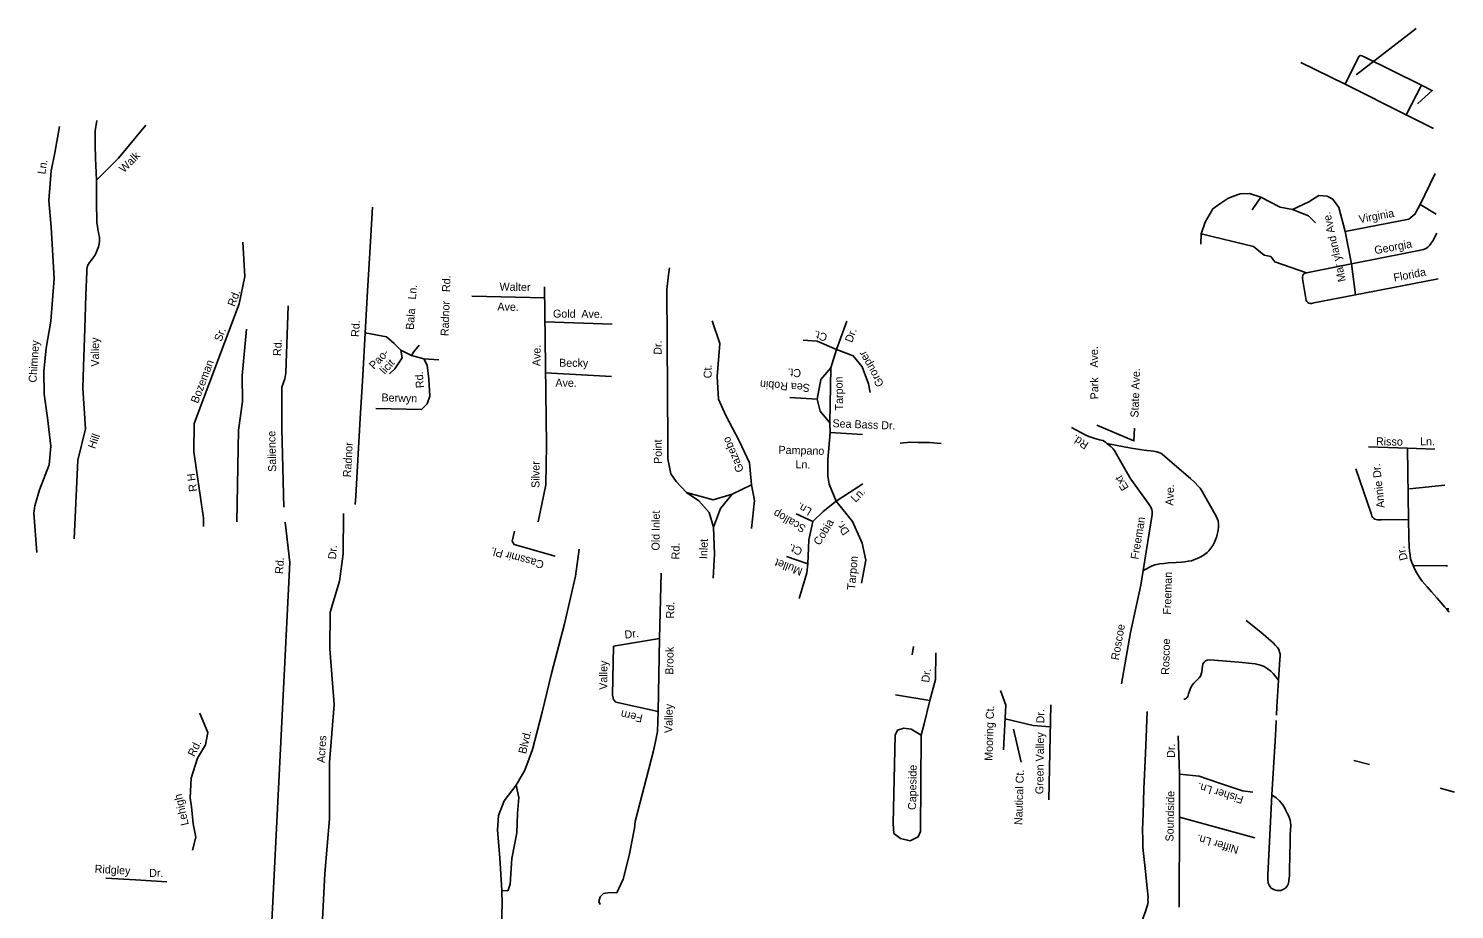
# Model space of a CAD drawing. Extents: x 2308163 to 2335412, y -96774 to 127732.
# Drawn here: x 2321991 to 2327836, y -48182 to -44573 of the extents above; entities that cross this region are included whole.
import ezdxf

# ---------------------------------------------------------------- set-up
doc = ezdxf.new("R2010")
doc.units = 0
doc.layers.add('Old_Level_10', color=7, linetype='Continuous')
doc.layers.add('Old_Level_35', color=7, linetype='Continuous')

msp = doc.modelspace()

# ---------------------------------------------------------------- linework, layer by layer
at = {"layer": 'Old_Level_10'}
for points in [[(2327678.5, -44572.8), (2327432.6, -44762.1)], [(2327745.2, -44824.8), (2327684.3, -44880.7)], [(2326523.7, -46210.6), (2326521.9, -46262.1), (2326369.2, -46197.5)], [(2326059.4, -47578.2), (2326027.9, -47443)]]:
    msp.add_lwpolyline(points, dxfattribs=at)
at = {"layer": 'Old_Level_35'}
for p, q in [((2327206.1, -44711.3), (2327387.1, -44800.8)), ((2327387.1, -44800.8), (2327638.1, -44926.8)), ((2327638.1, -44926.8), (2327701, -44805.4)), ((2327745.3, -44827.5), (2327701, -44805.4)), ((2327750.2, -44983), (2327638.1, -44926.8)), ((2327430.2, -45663.3), (2327413.2, -45536.7)), ((2322707.9, -46578.8), (2322669.1, -46307.3)), ((2327647.2, -46583.9), (2327642.9, -46292.4)), ((2323330.3, -46523), (2323332.3, -46488.5)), ((2322708, -46612.9), (2322707.9, -46578.8)), ((2325613.1, -47138.2), (2325617.8, -47104.3)), ((2327107.8, -47352.1), (2327113.9, -47242.5)), ((2326574.6, -47404.8), (2326575.9, -47370.7)), ((2327105.9, -47385.9), (2327107.8, -47352.1)), ((2326573.2, -47441.5), (2326574.6, -47404.8)), ((2327102.9, -47442.2), (2327100.9, -47491.3)), ((2327104.3, -47408.3), (2327102.9, -47442.2)), ((2327100.9, -47491.3), (2327087.7, -47712.1)), ((2327487.8, -47587.6), (2327423.2, -47571.1)), ((2327835.8, -47700.9), (2327777.6, -47684.6))]:
    msp.add_line(p, q, dxfattribs=at)
for points in [[(2327701, -44805.4), (2327462.8, -44687.6), (2327455.7, -44684), (2327449.8, -44683), (2327444.9, -44686), (2327442.8, -44690.1), (2327387.1, -44800.8)], [(2322099.2, -45082.6), (2322118.2, -44974.2)], [(2322269.8, -45194.2), (2322266.1, -45104.1), (2322264.4, -45051.1), (2322263.8, -45029.2), (2322264.7, -44992.1), (2322270.8, -44950.2)], [(2322472.4, -44968.1), (2322360.1, -45104.4), (2322269.8, -45194.2)], [(2322024.6, -46719.4), (2322012.8, -46558.4), (2322016.4, -46528.1), (2322036.4, -46462.8), (2322075.5, -46360.2), (2322083.1, -46284.4), (2322069.4, -46167.2), (2322055, -46070.3), (2322053.2, -45976.4), (2322064, -45882.9), (2322083.1, -45772), (2322096.7, -45597.4), (2322083.7, -45386.5), (2322074.7, -45277.1), (2322084, -45155.7), (2322099.2, -45082.6)], [(2327693.8, -45296.5), (2327756, -45166.6)], [(2322214.3, -46046.6), (2322216.4, -45957.4), (2322221.2, -45801.4), (2322225.5, -45664.6), (2322229.9, -45569.6), (2322230, -45558.5), (2322230.8, -45551.8), (2322232.4, -45544.5), (2322236.6, -45537.8), (2322241, -45531.9), (2322247.9, -45523), (2322255.2, -45513.1), (2322262.2, -45502.6), (2322267.9, -45491.7), (2322274, -45476.6), (2322277.3, -45466.6), (2322280, -45455.1), (2322281.4, -45444.6), (2322281.4, -45436.2), (2322281.3, -45427.7), (2322279.8, -45417.2), (2322278.3, -45408.7), (2322275.1, -45395.3), (2322273.2, -45383.1), (2322271.7, -45369.4), (2322269.8, -45280.3), (2322269.8, -45194.2)], [(2327413.2, -45536.7), (2327387.7, -45404.7), (2327361.4, -45306.2), (2327337.1, -45271.4), (2327314.2, -45260), (2327280.3, -45256.7), (2327239, -45282.9), (2327172.1, -45314.5), (2327121.5, -45304.3), (2327075.6, -45281.5), (2327042.3, -45263.4), (2326996, -45249.1), (2326957.8, -45249.9), (2326929.9, -45259.5), (2326906.2, -45269.3), (2326873.5, -45291.5), (2326845.2, -45311.8), (2326813.7, -45365.8), (2326797.1, -45414.1), (2326795.7, -45456.4)], [(2327042.3, -45263.4), (2327006.5, -45315.2)], [(2327387.7, -45404.7), (2327649.3, -45354.3), (2327673.4, -45334), (2327693.8, -45296.5)], [(2327761.2, -45333.6), (2327695, -45293.9)], [(2323332.3, -46488.5), (2323340.8, -46339.9), (2323350.8, -46170), (2323361.2, -45994.1), (2323371.3, -45819.4), (2323380.5, -45648.5), (2323390.3, -45491.7), (2323400.7, -45304.5)], [(2327172.1, -45314.5), (2327237.1, -45340.1), (2327265.8, -45368.7)], [(2327413.2, -45536.7), (2327641.4, -45491.2), (2327689.7, -45482.4), (2327702.8, -45479.7), (2327708.9, -45477.9), (2327715.9, -45474.9), (2327720.5, -45472.2), (2327726.1, -45468.3), (2327732.8, -45462), (2327740.4, -45452.6), (2327746.6, -45442.8), (2327763.7, -45411.3)], [(2322669.1, -46307.3), (2322670.1, -46191.4), (2322854.9, -45700.5), (2322877.1, -45588.4), (2322869.7, -45447.8)], [(2326797.1, -45414.1), (2327011.9, -45466), (2327055.3, -45501.5), (2327082.7, -45506.7), (2327098.9, -45528.4), (2327228.6, -45574.1)], [(2324797.1, -46824.3), (2324803.4, -46726.3), (2324798.5, -46616.4), (2324780.4, -46555.1), (2324738.7, -46507.4), (2324687.8, -46473.9), (2324646, -46429.1), (2324624, -46396.6), (2324611.6, -46335.5), (2324611, -46269.1), (2324606.7, -45642.1), (2324614.5, -45581.7), (2324618.4, -45553)], [(2327430.2, -45663.3), (2327259.4, -45697.1), (2327249.2, -45698.9), (2327244.8, -45698.9), (2327239.4, -45697.7), (2327235.3, -45695.5), (2327230.5, -45691.5), (2327227.3, -45686.4), (2327212.8, -45596.9), (2327212.9, -45590), (2327214, -45585), (2327216.1, -45580), (2327218.1, -45577.7), (2327223.3, -45575.1), (2327228.6, -45574.1), (2327413.2, -45536.7)], [(2324080.1, -46594.5), (2324111.4, -46442.5), (2324114.1, -46277.9), (2324106.3, -45631.6)], [(2327769.6, -45598.5), (2327621.3, -45626.9), (2327430.2, -45663.3)], [(2323808.5, -45669.4), (2324106.9, -45676.7)], [(2323037, -46534), (2323029.2, -46213.1), (2323029.3, -46042.6), (2323042.1, -46008.4), (2323045.8, -45984), (2323055.3, -45708.5)], [(2322844.5, -46593.5), (2322851.3, -46218.5), (2322868.3, -46100.6), (2322866.2, -45995.1), (2322884.3, -45805.1)], [(2323371.3, -45819.4), (2323458.8, -45836.5), (2323489.6, -45863.5), (2323517.6, -45890.5), (2323522.3, -45922.4), (2323491.8, -45967.6), (2323470.9, -45987.1)], [(2324108.1, -45775.1), (2324382.7, -45784.6)], [(2324954.8, -46442.7), (2324946.4, -46352.8), (2324903.2, -46261.8), (2324849, -46158.8), (2324819.5, -46091.4), (2324814, -45998.8), (2324824.5, -45863.4), (2324793, -45769.8)], [(2325301.7, -46509.5), (2325272.3, -46439.2), (2325267.6, -46407.2), (2325267.1, -46337.9), (2325276.7, -46228.5), (2325275.2, -46188), (2325280.1, -45962.8), (2325302.9, -45888.5), (2325344.5, -45771.5)], [(2323517.6, -45890.5), (2323560.2, -45912.2), (2323569.4, -45898.1), (2323592.9, -45869.6)], [(2325302.9, -45888.5), (2325223.1, -45854), (2325165.5, -45849.1)], [(2323611.8, -45925.5), (2323625.3, -45952), (2323632, -46010), (2323635.4, -46079.4), (2323625.6, -46110.9), (2323601.7, -46133.2), (2323414, -46129.6)], [(2323560.2, -45912.2), (2323611.8, -45925.5), (2323672.3, -45930.5)], [(2325302.9, -45888.5), (2325371.4, -45914), (2325407.4, -45958.6), (2325433.9, -46028.8), (2325441.4, -46063.7)], [(2324110.6, -45983.1), (2324381, -45998.5)], [(2325280.1, -45962.8), (2325238, -46010.5), (2325223.6, -46090.9), (2325236.4, -46140.4), (2325275.2, -46188)], [(2322214.3, -46046.6), (2322225.2, -46213.2), (2322192.9, -46341.4), (2322177.9, -46663.7)], [(2325223.6, -46090.9), (2325111.1, -46084.1)], [(2325276.7, -46228.5), (2325409.4, -46235.9)], [(2326265.6, -46207.6), (2326321.8, -46237), (2326336.7, -46244.3), (2326357.6, -46250.9), (2326380.3, -46257.3), (2326394.2, -46260.7), (2326405.2, -46266.9), (2326411, -46273.1)], [(2325731.4, -46272.3), (2325683.4, -46269.4), (2325637.9, -46269.1), (2325606.3, -46268), (2325564.4, -46271.6)], [(2326559.5, -46792.8), (2326597.1, -46564.5), (2326597.2, -46558.6), (2326596.4, -46550.8), (2326595.5, -46544.4), (2326594.5, -46540.3), (2326593, -46536.4), (2326584.1, -46522.5), (2326509.5, -46418.5), (2326496.1, -46396.1), (2326468.3, -46347.6), (2326450.9, -46317.2), (2326444.3, -46304.9), (2326436.5, -46294.8), (2326427.6, -46285.5), (2326411, -46273.1)], [(2326411, -46273.1), (2326510.6, -46291.6), (2326564.5, -46299.7), (2326602.4, -46304.6), (2326616.3, -46307), (2326624.2, -46309.3), (2326632.1, -46312.7), (2326638.2, -46316.6), (2326646.9, -46324.7), (2326707.7, -46377.4), (2326753.6, -46416.3), (2326773.2, -46434), (2326784.1, -46446), (2326792.8, -46456.3), (2326800.6, -46466.5), (2326812, -46488.9), (2326848.6, -46551.8), (2326859, -46570.9), (2326862.8, -46580.6), (2326866.6, -46590.1), (2326869, -46603.4), (2326868.9, -46616.2), (2326867.6, -46626.2), (2326866.2, -46635.2), (2326860.6, -46656.7), (2326852.5, -46676.9), (2326845.2, -46690.7), (2326837.8, -46701.6), (2326828.6, -46713.3), (2326822.5, -46719.2), (2326817.3, -46724), (2326805.5, -46732.2), (2326793.9, -46738.5), (2326781.2, -46744.7), (2326767.2, -46750.1), (2326758.4, -46753.3), (2326744.8, -46755.7), (2326730.6, -46758), (2326715, -46758.9), (2326694.5, -46760.2), (2326663.3, -46762.5), (2326646.3, -46764), (2326628.1, -46766.6), (2326608.1, -46770.1), (2326597, -46773.8), (2326559.5, -46792.8)], [(2327483.8, -46286.9), (2327642.9, -46292.4)], [(2327642.9, -46292.4), (2327755.3, -46296.2)], [(2327647.2, -46583.9), (2327537, -46585.3), (2327525, -46586), (2327521.1, -46585.9), (2327515, -46584.7), (2327509.4, -46583.3), (2327505.3, -46580.8), (2327500.5, -46576.1), (2327497.4, -46570.4), (2327494.7, -46560.2), (2327432, -46376.6)], [(2324798.5, -46616.4), (2324827.2, -46539.4), (2324875.5, -46480.4), (2324954.8, -46442.7), (2324967.1, -46506.6), (2324954.4, -46621.8)], [(2325301.7, -46509.5), (2325411.1, -46438.2)], [(2327796.2, -46443.5), (2327652, -46458.2)], [(2324687.8, -46473.9), (2324796.6, -46503.7), (2324875.5, -46480.4)], [(2325206.3, -46592.9), (2325248.2, -46551), (2325301.7, -46509.5), (2325368.2, -46592.7), (2325408.5, -46680.7), (2325423.5, -46750.6), (2325405.7, -46845.3)], [(2323172.5, -48678.1), (2323205.7, -48034.1), (2323224.4, -47811.2), (2323225, -47580.3), (2323244.2, -47342.7), (2323226.4, -47114.8), (2323227.9, -46964.5), (2323265.3, -46837.5), (2323280.2, -46724.4), (2323282.3, -46559.5)], [(2325185.9, -46765.5), (2325189.3, -46667.4), (2325206.3, -46592.9), (2325138, -46561.6)], [(2322968.4, -48639.6), (2323062.6, -46760.9), (2323042.6, -46595.3)], [(2324149.5, -46734.3), (2323981.4, -46686.6), (2323973.4, -46673.7), (2323982.4, -46631.5)], [(2327666.5, -46773.5), (2327660.8, -46760.3), (2327656.2, -46745.2), (2327653.5, -46731.1), (2327651.1, -46713.1), (2327649.5, -46696.1), (2327648.3, -46655.9), (2327647.2, -46583.9)], [(2324027.8, -48864.3), (2323998.2, -48813), (2323977.7, -48797.6), (2323932.3, -48534.3), (2323928.4, -48465), (2323925.3, -48372.8), (2323932.7, -48159.4), (2323930.4, -48104.8), (2323922.4, -47970.5), (2323913.8, -47857.1), (2323917.9, -47796.5), (2323941, -47736.6), (2323989.3, -47673.3), (2324024.9, -47611.7), (2324057.2, -47527), (2324096, -47373.3), (2324135, -47215.5), (2324188.1, -47012.1), (2324232.6, -46816.7), (2324247.7, -46706.5)], [(2325149.2, -46908.7), (2325181.7, -46802.9), (2325185.9, -46765.5), (2325097.3, -46736.4)], [(2324583.5, -46804.9), (2324577.6, -47072.4), (2324388.9, -47103.6), (2324385.1, -47304.5), (2324388.7, -47322.5), (2324398.8, -47333.3), (2324572.5, -47370.7), (2324577.6, -47072.4)], [(2326470.3, -47258), (2326507.3, -47046.8), (2326550, -46853.7), (2326559.5, -46792.8)], [(2327812.6, -46963.9), (2327812, -46963), (2327803.3, -46950.8), (2327795.5, -46941.6), (2327783, -46927.4), (2327763.4, -46905.9), (2327742.1, -46881.2), (2327724.5, -46860.8), (2327703.7, -46837.2), (2327691.6, -46819.2), (2327679.9, -46800.9), (2327672.3, -46786.6), (2327666.5, -46773.5)], [(2327806.6, -46773.7), (2327801.6, -46773.7), (2327666.5, -46773.5)], [(2327803.3, -46950.8), (2327812.2, -46950.2)], [(2327113.9, -47242.5), (2327120, -47157.5), (2327121.3, -47142.6), (2327121.1, -47135), (2327119.2, -47127.4), (2327116.9, -47120.5), (2327113.9, -47114.1), (2327109.1, -47107.2), (2327102.5, -47100.1), (2327092.6, -47089.8), (2327082.8, -47081.6), (2327041.6, -47046.6), (2326981.8, -46998.2)], [(2325710, -47130.7), (2325708.6, -47239.8), (2325685.4, -47325.6), (2325545.1, -47302.6)], [(2326726.7, -47320.8), (2326729.9, -47320.3), (2326733.5, -47318.5), (2326736.9, -47316.4), (2326739.5, -47313.4), (2326742.2, -47309.6), (2326745.4, -47298.6), (2326749.6, -47287.8), (2326754, -47275.9), (2326761.3, -47263.1), (2326767.5, -47255), (2326778.7, -47243.5), (2326789, -47232.6), (2326794.2, -47225.7), (2326797.6, -47217.8), (2326800.7, -47208), (2326801.9, -47196), (2326803.5, -47184.2), (2326804.5, -47178.6), (2326805.8, -47173.7), (2326809.7, -47168.6), (2326815.5, -47164.1), (2326821.8, -47161.3), (2326829.8, -47159.6), (2326850.8, -47161.2), (2326951.7, -47169.5), (2327005.5, -47174.8), (2327019.4, -47176.2), (2327035.5, -47179.4), (2327045.4, -47182.8), (2327056.4, -47187), (2327068.7, -47195), (2327083.4, -47206.4), (2327092.6, -47215.5), (2327113.9, -47242.5)], [(2325685.4, -47325.6), (2325662, -47421.5), (2325650.3, -47467.5), (2325646.8, -47862.3), (2325637.9, -47884.2), (2325605.1, -47901.2), (2325565.1, -47891.7), (2325537.6, -47870.6), (2325534.9, -47830.3), (2325543.4, -47467.8), (2325552.2, -47448), (2325578.7, -47438.8), (2325608.8, -47443.9), (2325650.3, -47467.5)], [(2325975.5, -47285.2), (2325997.4, -47344.4), (2325987, -47527.5)], [(2322691.8, -47377.4), (2322694.1, -47382.6), (2322725.6, -47456.5), (2322716.6, -47507.3), (2322683, -47562.2), (2322658.2, -47644.1), (2322653, -47724.3), (2322659.1, -47761), (2322666.4, -47831.9), (2322676.7, -47885.8), (2322662.7, -47938.9)], [(2324572.5, -47370.7), (2324569.7, -47452.3), (2324562.2, -47487.6), (2324553.3, -47532.3), (2324477.3, -47821.3), (2324474.3, -47849.4), (2324453.9, -47954.5), (2324450.1, -47972.2), (2324428.3, -48058.3), (2324402.3, -48114), (2324374, -48113), (2324347.6, -48117.3), (2324333.6, -48130.5), (2324328.7, -48149.2), (2324334.6, -48161.9)], [(2325994.2, -47400.4), (2326109.4, -47428.9), (2326179.1, -47433.6)], [(2326173.5, -47733.4), (2326180.7, -47344.1)], [(2326553.3, -48244), (2326555.7, -48235.6), (2326559.1, -48220.6), (2326562.3, -48207.6), (2326568.8, -48189.9), (2326574.3, -48173), (2326577.5, -48163.9), (2326578.6, -48157.1), (2326579.7, -48151.1), (2326578.9, -48142.1), (2326580.1, -48132.1), (2326576.2, -48092.9), (2326569.8, -48026.7), (2326561.5, -47952.5), (2326558.1, -47927.4), (2326558, -47894.5), (2326556.9, -47855.4), (2326559.4, -47790.5), (2326562.8, -47688.5), (2326569.3, -47543.6), (2326573.2, -47441.5)], [(2326708.5, -47627.4), (2326703.3, -47470.2)], [(2326706.7, -48172.6), (2326708.8, -47803.5), (2326708.5, -47627.4)], [(2326708.5, -47627.4), (2326788.8, -47636.5), (2326864.4, -47662.5), (2326967.3, -47695.7), (2327009.6, -47701.4)], [(2323989.3, -47673.3), (2324000.1, -47723.5), (2323995.8, -47788.3), (2323993, -47867.8), (2323972.6, -47973.9), (2323964.8, -48078.4), (2323957.7, -48103.3), (2323953.4, -48105.2), (2323930.4, -48104.8)], [(2327087.7, -47712.1), (2327070.6, -48041.8), (2327070.7, -48061.3), (2327072, -48074.2), (2327075.6, -48082.9), (2327079.7, -48089), (2327085, -48094.4), (2327089.3, -48097.3), (2327095.2, -48100.5), (2327101.8, -48102.8), (2327109, -48104.7), (2327115.2, -48105), (2327119, -48104.8), (2327124.9, -48103.8), (2327129.3, -48102.3), (2327135.9, -48099.5), (2327140.4, -48096.5), (2327144.4, -48093.6), (2327148.6, -48088.6), (2327151.7, -48083.9), (2327153.8, -48078.9), (2327155.6, -48072.5), (2327156.5, -48067.8), (2327157.5, -48061.7), (2327158.4, -48055), (2327159.7, -48043), (2327159.9, -48028.9), (2327160.2, -48020), (2327162, -47904.9), (2327162.6, -47875.9), (2327163.8, -47855.4), (2327164.6, -47838), (2327163.7, -47823.9), (2327161.8, -47816.7), (2327159.3, -47807.8), (2327155.4, -47797.2), (2327150.5, -47787.5), (2327145.1, -47776.4), (2327140, -47767.4), (2327131.7, -47754), (2327124.9, -47744.9), (2327119, -47737.7), (2327104.8, -47725.3), (2327087.7, -47712.1)], [(2326708.8, -47803.5), (2327018, -47888.5)], [(2322307.9, -48053.3), (2322429.5, -48060.4), (2322558.3, -48069.2)]]:
    msp.add_lwpolyline(points, dxfattribs=at)

# ---------------------------------------------------------------- texts
at = {"layer": 'Old_Level_10'}
for s, height, rotation, p in [('Ln.', 32.81, 80.18579, (2322059.1, -45171.9)), ('Walk', 32.81, 45.38719, (2322382.3, -45165.9)), ('Mar yland Ave.', 32.808, 102.8292, (2327391, -45606.8)), ('Virginia', 32.81, 10.49306, (2327446.8, -45370.5)), ('Georgia', 32.81, 10.48126, (2327510.5, -45497.8)), ('Radnor   Rd.', 32.808, 88.15233, (2323712.7, -45833.3)), ('Florida', 32.81, 11.00888, (2327589.3, -45610)), ('Bala   Ln.', 32.81, 85.75423, (2323569.7, -45808.1)), ('Walter', 32.81, 358.73813, (2323921.4, -45646.1)), ('Bozeman       Sr.        Rd.', 32.808, 69.19482, (2322685.2, -46111)), ('Ave.', 32.81, 358.73813, (2323912.6, -45728)), ('Gold', 32.81, 359.40928, (2324140.7, -45757)), ('Ave.', 32.81, 359.40928, (2324256.8, -45758)), ('Rd.', 32.81, 86.93568, (2323345.7, -45837.3)), ('Ct.', 32.81, 163.82832, (2325268, -45824.6)), ('Dr.', 32.81, 69.38486, (2325366.5, -45862.1)), ('Chimney', 32.81, 86.24859, (2322023.6, -46024.3)), ('Valley', 32.81, 90.4143, (2322280.2, -45957.9)), ('Rd.', 32.81, 87.60863, (2323026.3, -45915)), ('Ave.', 32.81, 89.52292, (2324089.4, -45956.3)), ('Dr.', 32.81, 89.4605, (2324586, -45909.3)), ('Ave.', 32.81, 90.57036, (2326375.3, -45962)), ('Pao-', 32.81, 46.90689, (2323407.4, -45971.6)), ('licit', 32.81, 46.90689, (2323450.9, -45991.9)), ('Becky', 32.81, 359.39522, (2324165.6, -45958.4)), ('Grouper', 32.81, 119.42301, (2325498.6, -46029.8)), ('Rd.', 32.81, 94.31649, (2323611.9, -46045)), ('Ct.', 32.81, 91.0081, (2324791.5, -46005.6)), ('Ct.', 32.81, 175.71507, (2325158.8, -45969.4)), ('State Ave.', 32.81, 88.02472, (2326540.2, -46167)), ('Ave.', 32.81, 359.39522, (2324150.5, -46040.3)), ('       Sea Robin ', 32.808, 175.71507, (2325279.7, -46036.1)), ('Tarpon', 32.81, 90.96878, (2325329.9, -46137.4)), ('Park', 32.81, 90.57036, (2326376.5, -46092)), ('Berwyn', 32.81, 358.1695, (2323437.4, -46100.3)), ('Sea Bass Dr.', 32.808, 357.76224, (2325285.9, -46206.2)), ('Hill ', 32.81, 70.57017, (2322264.2, -46297.2)), ('Salience', 32.81, 91.3925, (2323006.4, -46388.8)), ('Radnor', 32.81, 86.71925, (2323312, -46412.1)), ('Point', 32.81, 90.4182, (2324587, -46356.3)), ('Gazebo', 32.81, 113.08233, (2324924.1, -46382.8)), ('Pampano ', 32.81, 358.56772, (2325064.7, -46315.1)), ('Rd.', 32.81, 147.56716, (2326339.3, -46271.4)), ('Risso', 32.81, 359.23122, (2327514.1, -46280.3)), ('Ln.', 32.81, 359.78718, (2327694.9, -46280.6)), ('Silver', 32.81, 89.52253, (2324085.2, -46455.2)), ('Ln.', 32.81, 358.56772, (2325134.3, -46374.2)), ('R H', 32.81, 97.68715, (2322682.3, -46468.3)), ('Ext', 32.81, 120.87874, (2326502, -46454)), ('Annie Dr.', 32.81, 96.08257, (2327549.9, -46535.8)), ('Ave.', 32.81, 88.36506, (2326683.5, -46527.9)), ('Ln.', 32.81, 150.38519, (2325204.8, -46542.2)), ('Ln.', 32.81, 45.7345, (2325381, -46516.6)), ('Old Inlet', 32.81, 89.48366, (2324577.5, -46711.6)), ('Scallop ', 32.81, 150.38519, (2325180.6, -46612.3)), ('Freeman', 32.81, 80.65612, (2326539.8, -46749.6)), ('Cobia', 32.81, 58.95245, (2325234.2, -46693)), ('Dr.', 32.81, 125.53608, (2325358.1, -46634)), ('Dr.', 32.81, 85.98926, (2323251.4, -46748.3)), ('Cassmir Pl.', 32.808, 164.86716, (2324106.4, -46755.4)), ('Rd.', 32.81, 89.48366, (2324659.2, -46748)), ('Inlet', 32.81, 88.02472, (2324772.8, -46747)), ('Ct.', 32.81, 159.12015, (2325166.1, -46702.7)), ('Dr.', 32.81, 104.75812, (2327644.6, -46747.6)), ('Rd.', 32.81, 85.89384, (2323033.9, -46808.4)), ('Mullet', 32.81, 159.12015, (2325166.7, -46785.4)), ('Tarpon', 32.81, 84.96368, (2325378.4, -46873.6)), ('Freeman', 32.81, 88.36506, (2326673.2, -46974.7)), ('Rd.', 32.81, 89.1148, (2324637.2, -46990)), ('Dr.', 32.81, 7.31703, (2324436.1, -47072.7)), ('Roscoe', 32.81, 79.98655, (2326459.5, -47162.5)), ('Brook', 32.81, 89.11451, (2324633.7, -47220.4)), ('Roscoe ', 32.81, 88.36506, (2326666.1, -47221.1)), ('Valley', 32.81, 89.34598, (2324362.8, -47282.2)), ('Dr.', 32.81, 82.12929, (2325682.6, -47253.9)), ('Valley', 32.81, 89.11338, (2324630, -47459.6)), ('Fern', 32.81, 167.80014, (2324510.7, -47384.6)), ('Mooring Ct.', 32.808, 88.26116, (2325942, -47573.5)), ('Green Valley   Dr.', 32.808, 89.29644, (2326150.6, -47709.9)), ('Blvd.', 32.81, 76.55392, (2324029.9, -47546.9)), ('Rd.', 32.81, 63.66991, (2322671, -47558.8)), ('Acres', 32.81, 86.63312, (2323205.4, -47582.3)), ('Dr.', 32.81, 89.64489, (2326689.6, -47561)), ('Capeside', 32.81, 89.10122, (2325628.7, -47774.8)), ('Nautical Ct.', 32.808, 88.02472, (2326063.7, -47836.6)), ('Fisher Ln.', 32.81, 162.94304, (2326973.9, -47718.7)), ('Lehigh', 32.81, 103.2557, (2322648.3, -47834.3)), ('Soundside ', 32.81, 88.85475, (2326683.8, -47903.9)), ('Niffer Ln.', 32.81, 163.63217, (2326954.4, -47924.1)), ('Ridgley', 32.81, 356.74322, (2322261.5, -48031.5)), ('Dr.', 32.81, 359.02815, (2322485.1, -48048.4))]:
    msp.add_text(s, height=height, rotation=rotation, dxfattribs=at).set_placement(p)

doc.saveas('drawing.dxf')
